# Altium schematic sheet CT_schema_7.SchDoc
size 274 x 160 mm
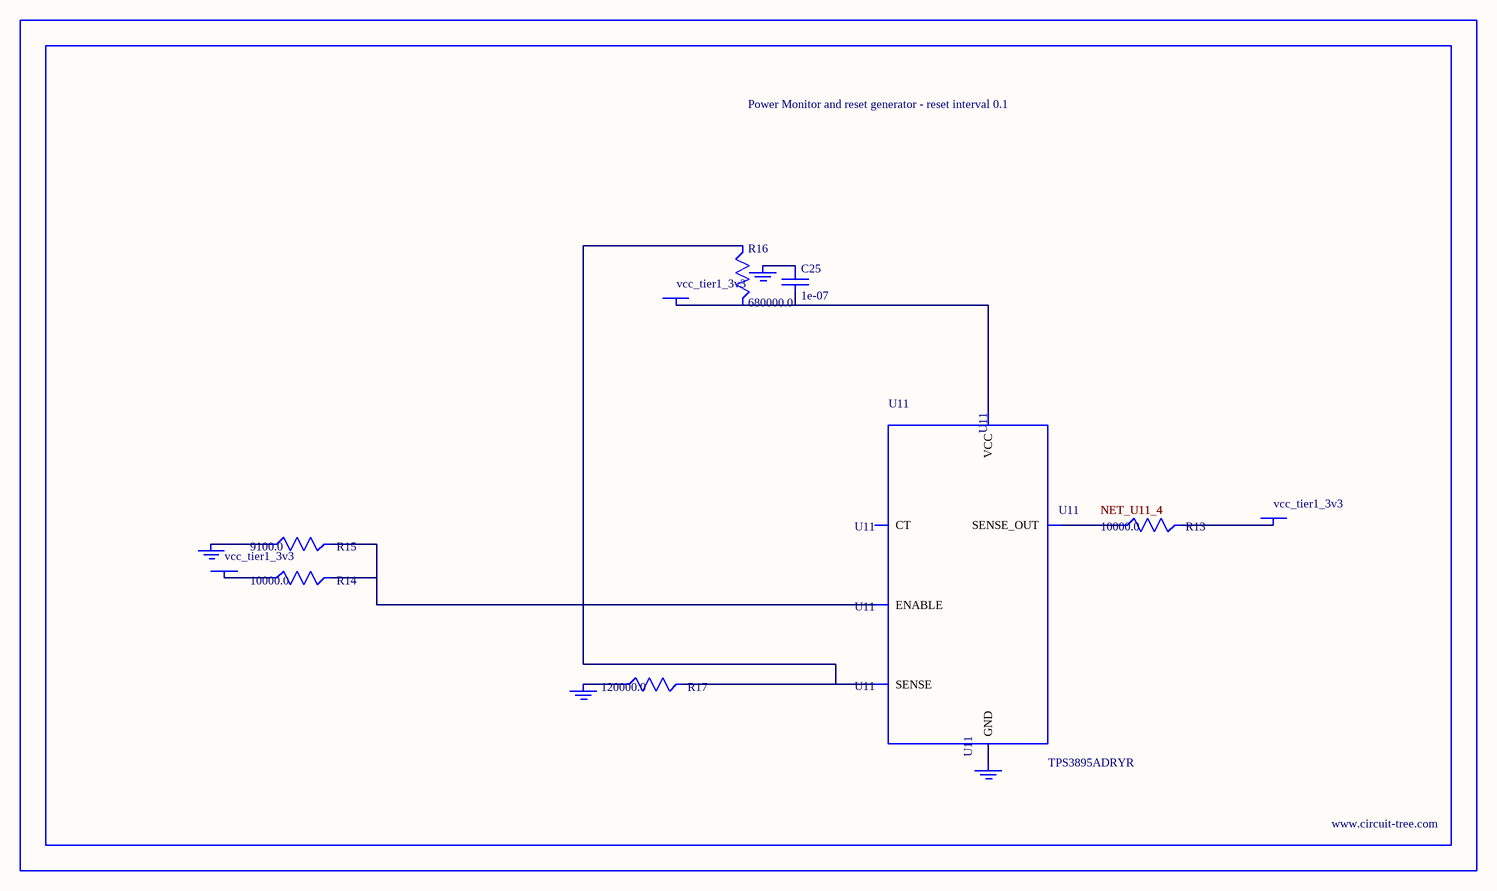
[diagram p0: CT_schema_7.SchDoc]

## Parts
BORDER6  (no value)
C25  1e-07  [C0402]
GND_INSTANCE_6_0  (no value)
GND_INSTANCE_6_1  (no value)
GND_INSTANCE_6_2  (no value)
GND_INSTANCE_6_3  (no value)
POWER_INSTANCE_6_0  vcc_tier1_3v3
POWER_INSTANCE_6_1  vcc_tier1_3v3
POWER_INSTANCE_6_2  vcc_tier1_3v3
R13  10000.0  [R0603]
R14  10000.0  [R0603]
R15  9100.0  [R0603]
R16  680000.0  [R0603]
R17  120000.0  [R0603]
U11  TPS3895ADRYR  [SON-6]

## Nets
NetC25_1: C25.1 GND_INSTANCE_6_2.0(GND)
NetC25_2: C25.2 POWER_INSTANCE_6_2.0(PWR) R16.2 U11.6(VCC)
NetGND_INSTANCE_6_0_0: GND_INSTANCE_6_0.0(GND) R15.1
NetGND_INSTANCE_6_1_0: GND_INSTANCE_6_1.0(GND) R17.1
NetGND_INSTANCE_6_3_0: GND_INSTANCE_6_3.0(GND) U11.2(GND)
NetPOWER_INSTANCE_6_0_0: POWER_INSTANCE_6_0.0(PWR) R14.1
NetPOWER_INSTANCE_6_1_0: POWER_INSTANCE_6_1.0(PWR) R13.2
NetR13_1: R13.1 U11.4(SENSE_OUT)
NetR14_2: R14.2 R15.2 U11.1(ENABLE)
NetR16_1: R16.1 R17.2 U11.3(SENSE)

Not connected (* = marked no-connect by the designer): U11 5(CT)

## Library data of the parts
BORDER6 = BORDER_PAGE6
C25 = C0402C104K3RACTU
GND_INSTANCE_6_0-GND_INSTANCE_6_3 = GND
POWER_INSTANCE_6_0-POWER_INSTANCE_6_2 = PWR
R13 R14 = RC0603JR-0710KL
R15 = RC0603JR-079K1L
R16 = RC0603JR-07680KL
R17 = RC0603JR-07120KL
